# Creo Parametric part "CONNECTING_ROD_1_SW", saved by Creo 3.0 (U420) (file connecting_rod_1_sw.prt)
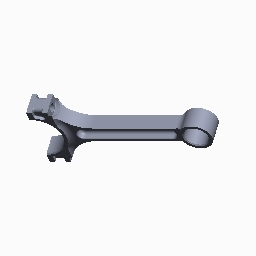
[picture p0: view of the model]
Units: millimeter Kilogram Sec (mmKs); MM, KILOGRAM, SECS

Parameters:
  CAD_SYSTEM = "SOLIDWORKS_PART"
  DEX_MASTER = "connecting_rod_1_sw(109,509)"
  MODEL_VERSION = "174"
  MODEL_DATE = "12/13/2013 06:16:28"
  TIM_STATUS = "Missing Ref Model"
  REF_LINK = "D:\009_demo_dev\001_Creo_Trail\engine_shaft_asm_v5\connecting_rod_1_sw.SLDPRT"
  NATIVE_NAME = "connecting_rod_1_sw(109,509)"

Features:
  1. coordinate system "CONNECTING_ROD_1_SW"
  2. imported feature "Import Feature id 4"

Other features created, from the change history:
  component interface "INTFC001"

Layers: SHELL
